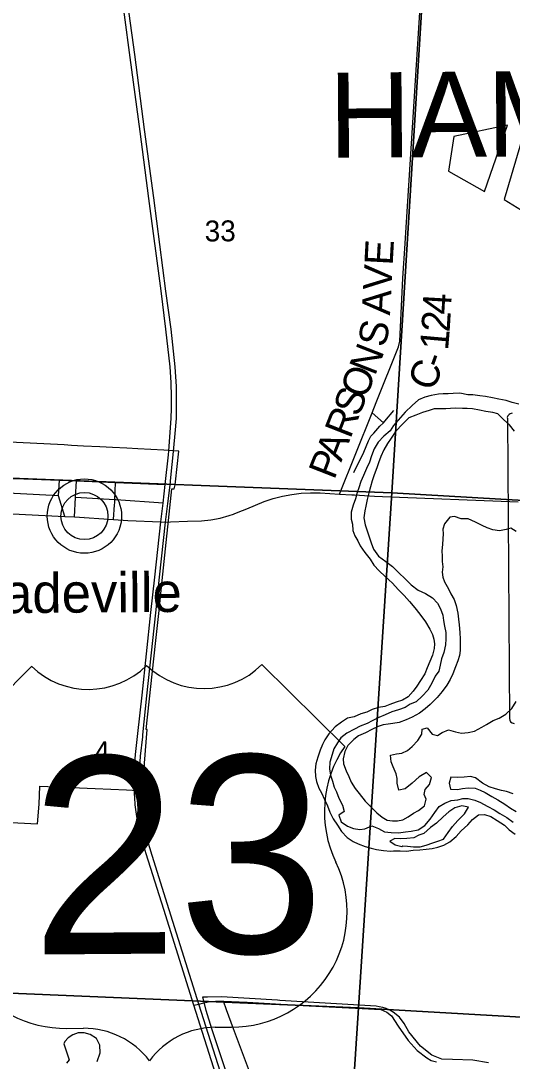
# Model space of a CAD drawing. Extents: x 114604 to 551442, y 316898 to 567001.
# Drawn here: x 204563 to 209759, y 333844 to 344839 of the extents above; entities that cross this region are included whole.
import ezdxf

# ---------------------------------------------------------------- set-up
doc = ezdxf.new("R2010")
doc.units = 0
for name, color, linetype in [('_CIVIL_CONSTRUCTION', 7, 'Continuous'), ('DV_X_County_Line', 7, 'Continuous'), ('GE_P_Alignment_1000_Cardinal_Points', 7, 'Continuous'), ('GE_P_Alignment_1000_Stations', 7, 'Continuous'), ('GE_P_Alignment_100_Stations', 7, 'Continuous'), ('GE_P_Alignment_500_Bearings', 7, 'Continuous'), ('GE_P_Alignment_500_Cardinal_Points', 7, 'Continuous'), ('GE_P_Alignment_500_Curve_Data', 7, 'Continuous'), ('GE_P_Alignment_500_Stations', 7, 'Continuous'), ('GE_X_Alignment', 7, 'Continuous'), ('MT_X_Edge_Line', 7, 'Continuous'), ('PM_P_CL_Double_Solid', 7, 'Continuous'), ('PM_X_Dotted_Line', 7, 'Continuous'), ('PV_X_Curb', 7, 'Continuous'), ('RD_X_RR_1', 7, 'Continuous'), ('SN_P_Signs', 7, 'Continuous')]:
    doc.layers.add(name, color=color, linetype=linetype)

msp = doc.modelspace()

# ---------------------------------------------------------------- linework, layer by layer
at = {"layer": '_CIVIL_CONSTRUCTION'}
for p, q in [((208090, 339829), (208302, 339817)), ((206094, 339542), (206146, 339544))]:
    msp.add_line(p, q, dxfattribs=at)
for points in [[(206818, 339628), (206860, 339645), (206952, 339683), (207043, 339722), (207138, 339758), (207232, 339790), (207329, 339815), (207428, 339833), (207526, 339846), (207626, 339850), (207729, 339849), (207932, 339838), (208064, 339830), (208090, 339829)], [(208302, 339817), (208386, 339813), (209824, 339754)], [(204265, 339638), (205029, 339601), (205130, 339596), (205544, 339568), (205696, 339559), (206045, 339544), (206094, 339542)], [(206146, 339544), (206324, 339550), (206472, 339554), (206572, 339564), (206670, 339582), (206766, 339610), (206813, 339626), (206818, 339628)]]:
    msp.add_lwpolyline(points, dxfattribs=at)
at = {"layer": 'DV_X_County_Line'}
for points in [[(209695, 340825), (209617, 340840), (209551, 340856), (209477, 340870), (209417, 340875), (209343, 340885), (209289, 340888), (209205, 340904), (209135, 340899), (209083, 340897), (209031, 340897), (208980, 340895), (208902, 340880), (208834, 340862), (208770, 340835), (208701, 340773), (208627, 340704), (208504, 340563), (208469, 340507), (208403, 340450), (208343, 340386), (208300, 340314), (208272, 340241), (208249, 340175), (208217, 340107), (208188, 340035), (208158, 339972), (208139, 339904), (208121, 339854), (208101, 339788), (208078, 339720), (208056, 339645), (208057, 339573), (208069, 339521), (208073, 339453), (208094, 339395), (208126, 339344), (208152, 339290), (208201, 339220), (208259, 339148), (208297, 339086), (208354, 339027), (208416, 338965), (208492, 338895), (208555, 338830), (208617, 338766), (208673, 338702), (208730, 338634), (208782, 338569), (208842, 338487), (208887, 338409), (208915, 338355), (208931, 338305), (208936, 338255), (208934, 338205), (208916, 338135), (208889, 338069), (208861, 338001), (208834, 337936), (208790, 337868), (208752, 337806), (208713, 337755), (208659, 337695), (208598, 337658), (208534, 337638), (208466, 337612), (208412, 337593), (208344, 337581), (208279, 337562), (208221, 337532), (208157, 337514), (208089, 337485), (208019, 337469), (207954, 337428), (207886, 337376), (207821, 337303), (207777, 337241), (207753, 337191), (207730, 337132), (207704, 337056), (207683, 336988), (207675, 336920), (207680, 336854), (207690, 336800), (207716, 336730), (207741, 336680), (207773, 336608), (207807, 336542), (207830, 336476), (207866, 336406), (207912, 336337), (207953, 336271), (208013, 336209), (208079, 336167), (208131, 336140), (208203, 336112), (208267, 336094), (208325, 336081), (208397, 336069), (208471, 336062)], [(209606, 340684), (209554, 340698), (209482, 340711), (209414, 340725), (209338, 340739), (209284, 340742), (209232, 340742), (209162, 340745), (209108, 340743), (209056, 340739), (209004, 340737), (208935, 340738), (208881, 340722), (208809, 340699), (208739, 340671), (208665, 340642), (208600, 340578), (208528, 340503), (208479, 340429), (208441, 340371), (208402, 340306), (208370, 340236), (208347, 340168), (208329, 340114), (208300, 340041), (208278, 339977), (208260, 339913), (208243, 339851), (208225, 339781), (208210, 339710), (208200, 339660), (208192, 339588), (208203, 339514), (208225, 339450), (208246, 339386), (208268, 339322), (208292, 339254), (208347, 339183), (208423, 339125), (208495, 339072), (208559, 339004), (208626, 338942), (208692, 338878), (208764, 338821), (208844, 338785), (208915, 338742), (208971, 338686), (209001, 338624), (209024, 338558), (209034, 338502), (209044, 338442), (209057, 338376), (209059, 338306), (209053, 338244), (209038, 338162), (209010, 338098), (208999, 338031), (208983, 337965), (208944, 337913), (208908, 337839), (208867, 337766), (208807, 337700), (208742, 337641), (208680, 337617), (208626, 337581), (208556, 337556), (208486, 337536), (208415, 337503), (208349, 337475), (208277, 337442), (208226, 337414), (208150, 337383), (208090, 337353), (208012, 337310), (207947, 337262), (207911, 337208), (207874, 337145), (207854, 337085), (207832, 337005), (207829, 336935), (207839, 336867), (207858, 336805), (207878, 336741), (207900, 336689), (207927, 336623), (207965, 336549), (207983, 336483), (207926, 336445), (207952, 336373), (208016, 336327), (208082, 336302), (208148, 336294), (208200, 336300), (208276, 336331), (208344, 336303), (208410, 336268), (208480, 336260), (208558, 336258), (208630, 336269), (208692, 336275), (208766, 336288)], [(209829, 340786), (209759, 340807), (209695, 340825)], [(209783, 340501), (209731, 340569), (209670, 340622), (209606, 340684)], [(208766, 336288), (208835, 336334), (208893, 336403), (208940, 336471), (208988, 336535), (209046, 336570), (209115, 336600), (209185, 336607), (209237, 336619), (209293, 336621), (209365, 336604), (209425, 336578), (209495, 336539)], [(209296, 336529), (209228, 336543), (209152, 336522), (209088, 336480), (209028, 336428), (208959, 336361), (208895, 336313), (208824, 336252), (208772, 336232), (208720, 336205), (208644, 336199), (208580, 336193), (208518, 336198), (208467, 336170), (208523, 336130), (208591, 336112)], [(208591, 336112), (208601, 336119), (208653, 336115), (208717, 336109), (208787, 336108), (208851, 336126), (208920, 336153), (208972, 336169), (209034, 336191), (209083, 336260), (209129, 336324), (209185, 336388), (209256, 336457), (209296, 336529)], [(209495, 336539), (209503, 336535), (209569, 336501), (209630, 336461), (209702, 336418), (209768, 336370)], [(208471, 336062), (208503, 336068), (208575, 336068), (208643, 336065), (208713, 336073), (208783, 336076), (208849, 336084), (208913, 336092), (208973, 336105), (209036, 336127), (209098, 336162), (209168, 336218), (209221, 336279), (209289, 336343), (209340, 336399), (209402, 336446), (209468, 336452), (209534, 336429), (209602, 336389), (209678, 336339), (209728, 336290), (209789, 336244)]]:
    msp.add_lwpolyline(points, dxfattribs=at)
at = {"layer": 'GE_P_Alignment_1000_Cardinal_Points'}
for p, q in [((208278, 340697), (208397, 340592)), ((205557, 339777), (205141, 339802)), ((205544, 339568), (205554, 339723))]:
    msp.add_line(p, q, dxfattribs=at)
for points in [[(208084, 340065), (208191, 340282), (208241, 340400), (208263, 340448), (208295, 340482), (208361, 340554), (208397, 340592), (208411, 340608), (208507, 340722)], [(204326, 340003), (204437, 340002), (204501, 340001), (204971, 339983), (205151, 339976)], [(205029, 339601), (204962, 339818), (204971, 339983)], [(205130, 339596), (205141, 339802), (205151, 339976)], [(205151, 339976), (205566, 339961), (206090, 339937)], [(205554, 339723), (205556, 339744), (205557, 339777), (205566, 339961)], [(204962, 339818), (204425, 339848), (204274, 339856)], [(206067, 339743), (205571, 339776), (205557, 339777)], [(207356, 331404), (207410, 331406), (207824, 331419), (207653, 331891), (207380, 332658), (207243, 333036), (207025, 333622), (206813, 334185), (206738, 334385), (206705, 334477)]]:
    msp.add_lwpolyline(points, dxfattribs=at)
at = {"layer": 'GE_P_Alignment_1000_Stations'}
for p, q in [((205981, 338961), (206045, 339544)), ((206031, 338961), (206094, 339542))]:
    msp.add_line(p, q, dxfattribs=at)
for points in [[(206182, 340326), (206196, 340477), (206208, 340636), (206209, 340798), (206208, 340976), (206197, 341181), (206152, 341582), (206097, 341982), (205970, 342969), (205872, 343691), (205768, 344484), (205650, 345353), (205382, 347391), (205104, 349623), (205005, 350415), (204967, 350703), (204739, 352561), (204719, 352732)], [(206124, 340251), (206128, 340293), (206152, 340637), (206157, 340746), (206157, 340864), (206154, 341016), (206143, 341181), (206098, 341580), (206046, 341986), (205916, 342960), (205824, 343668), (205718, 344453), (205599, 345356), (205331, 347383), (205052, 349604), (204952, 350404), (204916, 350706), (204688, 352542), (204683, 352579)], [(206150, 340012), (206179, 340289), (206182, 340326)], [(206045, 339544), (206067, 339743), (206090, 339937), (206124, 340251)], [(206094, 339542), (206119, 339739), (206141, 339933), (206150, 340012)], [(205767, 336631), (205765, 336667), (205761, 336775), (205763, 336892), (205775, 337084), (205800, 337307), (205846, 337711), (205939, 338585), (205981, 338961)], [(205852, 337273), (205854, 337294), (205897, 337707), (205990, 338581), (206031, 338961)], [(205820, 336639), (205815, 336698), (205815, 336827), (205828, 337066), (205852, 337273)], [(207213, 331853), (207164, 332008), (206969, 332619), (206647, 333636), (206394, 334435), (206074, 335447), (205889, 336035), (205837, 336213), (205812, 336322), (205791, 336431), (205773, 336554), (205767, 336631)], [(206446, 334448), (206132, 335443), (205951, 336017), (205904, 336181), (205870, 336298), (205850, 336411), (205826, 336563), (205820, 336639)], [(207331, 331656), (207216, 332020), (207021, 332632), (206700, 333649), (206446, 334448)]]:
    msp.add_lwpolyline(points, dxfattribs=at)
at = {"layer": 'GE_P_Alignment_100_Stations'}
for points in [[(204111, 336384), (204741, 336353), (204757, 336559), (204765, 336751), (205351, 336726), (205679, 336712), (205872, 336703), (205871, 336995), (205899, 337348), (205888, 337349), (205986, 338257), (206021, 338576), (206059, 338925), (206159, 339892), (206185, 339893), (206196, 339935), (206199, 339967), (206235, 340292), (206076, 340300), (205800, 340315), (205684, 340321), (205532, 340329), (205399, 340336), (205225, 340345), (205100, 340351), (205021, 340357), (204082, 340403)], [(209510, 333828), (209344, 333856), (209129, 333861), (209016, 333864), (208908, 333909), (208791, 334002), (208665, 334156), (208616, 334241), (208566, 334309), (208501, 334363), (208464, 334383), (208426, 334401), (208392, 334412), (208352, 334420), (208321, 334424), (207301, 334486), (207278, 334488), (206685, 334524), (206536, 334522), (206484, 334522), (206520, 334384), (206579, 334189), (206628, 334042), (206800, 333525)]]:
    msp.add_lwpolyline(points, dxfattribs=at)
at = {"layer": 'GE_P_Alignment_500_Bearings'}
for points in [[(208628, 342485), (208628, 342490), (208790, 345040), (208827, 345709), (208918, 347356), (208993, 348382)], [(207932, 339838), (208278, 340697), (208321, 340807), (208556, 341393), (208570, 341454), (208604, 342121), (208628, 342485)], [(206394, 334435), (206446, 334448), (206497, 334462), (206561, 334475), (206622, 334480), (206705, 334477), (206955, 334467), (207613, 334429), (208171, 334400), (208371, 334390), (208435, 334363), (208484, 334323), (208554, 334215), (208660, 334063), (208754, 333958), (208858, 333878), (208904, 333852), (208958, 333838)]]:
    msp.add_lwpolyline(points, dxfattribs=at)
at = {"layer": 'GE_P_Alignment_500_Cardinal_Points'}
for p, q in [((204675, 338017), (203811, 337141)), ((207988, 337171), (207112, 338035)), ((205051, 334191), (205225, 334192)), ((206617, 334202), (206791, 334203))]:
    msp.add_line(p, q, dxfattribs=at)
for centre, radius, start, end in [((205280, 338643), 870, 225.9863, 314.8403), ((206498, 338652), 870, 225.9863, 314.8403), ((208991, 336479), 1218, 145.4124, 205.8662), ((205029, 335409), 1218, 155.2452, 271.0516), ((206796, 335422), 1218, 269.7751, 25.5814), ((205231, 333322), 870, 37.2832, 90.4133), ((206624, 333332), 870, 90.4133, 143.5434)]:
    msp.add_arc(centre, radius, start, end, dxfattribs=at)
at = {"layer": 'GE_P_Alignment_500_Curve_Data'}
msp.add_line((209708, 340636), (209731, 337466), dxfattribs=at)
for centre, major_axis, start_param, end_param in [((209768, 340644), (60.5, 0.4), 1.712693, 3.28349), ((209792, 337460), (61, 0.4), 3.00124, 4.508301)]:
    msp.add_ellipse(centre, major_axis=major_axis, ratio=0.8, start_param=start_param, end_param=end_param, dxfattribs=at)
at = {"layer": 'GE_X_Alignment'}
for radius in [393, 249]:
    msp.add_circle((205236, 339605), radius, dxfattribs=at)
at = {"layer": 'MT_X_Edge_Line'}
for points in [[(209711, 343736), (209141, 343617), (209087, 343251), (209467, 343036)], [(209467, 343036), (209711, 343736)], [(209885, 343666), (209676, 342949), (209857, 342837), (209897, 342833), (210273, 343211)], [(209800, 339443), (209744, 339477), (209694, 339462), (209624, 339450), (209554, 339459), (209496, 339479), (209441, 339505), (209371, 339540), (209295, 339576), (209221, 339577), (209150, 339599), (209098, 339592), (209045, 339522), (209027, 339468), (209028, 339416), (209026, 339366), (209022, 339306), (209015, 339236), (209017, 339180), (209020, 339124), (209024, 339070), (209020, 339013), (209025, 338959), (209043, 338909), (209084, 338837), (209112, 338784), (209144, 338722), (209165, 338660), (209185, 338580), (209192, 338516), (209200, 338455), (209207, 338375), (209209, 338305), (209208, 338185), (209203, 338133), (209183, 338075), (209161, 338011), (209132, 337939), (209102, 337877), (209067, 337819), (209017, 337752), (208965, 337686), (208892, 337614), (208840, 337568), (208778, 337521), (208703, 337481), (208637, 337450), (208565, 337424), (208497, 337412), (208447, 337405), (208395, 337399), (208343, 337381), (208275, 337350), (208207, 337314), (208135, 337283), (208084, 337243), (208020, 337179), (207990, 337117), (207973, 337039), (207977, 336985), (208004, 336913), (208030, 336853), (208055, 336794), (208097, 336726), (208140, 336672), (208204, 336591), (208275, 336521), (208329, 336468), (208384, 336424), (208436, 336391), (208494, 336385), (208548, 336384), (208602, 336394), (208658, 336426), (208714, 336465), (208767, 336493), (208831, 336541), (208851, 336613), (208828, 336663), (208840, 336715), (208884, 336767), (208905, 336843), (208853, 336895), (208775, 336850), (208703, 336782), (208628, 336724), (208562, 336707), (208543, 336781), (208543, 336831), (208533, 336881), (208500, 336956), (208480, 337006), (208471, 337078), (208535, 337092), (208591, 337101), (208653, 337129), (208703, 337171)], [(208703, 337171), (208760, 337232), (208802, 337300), (208806, 337352), (208860, 337366), (208914, 337299), (208970, 337285), (209020, 337317), (209086, 337346), (209158, 337326), (209224, 337309), (209292, 337317), (209362, 337331), (209438, 337374), (209488, 337402), (209558, 337443), (209622, 337469), (209691, 337513), (209755, 337570), (209802, 337644)], [(209769, 336669), (209699, 336693), (209645, 336706), (209583, 336722), (209514, 336743), (209444, 336783), (209370, 336840), (209317, 336854), (209251, 336844), (209177, 336841), (209111, 336845), (209094, 336781), (209106, 336719), (209180, 336717), (209234, 336726), (209292, 336734), (209366, 336728), (209421, 336707), (209473, 336683), (209543, 336642), (209607, 336606), (209680, 336561), (209742, 336519), (209802, 336484)], [(205372, 333842), (205402, 333933), (205400, 334013), (205364, 334083), (205298, 334127), (205234, 334145), (205168, 334143), (205112, 334123), (205064, 334091), (205028, 334051), (205018, 334029)], [(205018, 334029), (205075, 333859)], [(205075, 333859), (205045, 333823)]]:
    msp.add_lwpolyline(points, dxfattribs=at)
at = {"layer": 'PM_X_Dotted_Line'}
msp.add_line((205236, 339605), (205236, 339605), dxfattribs=at)
at = {"layer": 'SN_P_Signs'}
for points in [[(203568, 345444), (208815, 345168), (208486, 339851), (204088, 340018)], [(204088, 340018), (208486, 339851), (208133, 334409), (202949, 334626)]]:
    msp.add_lwpolyline(points, dxfattribs=at)
for points in [[(208815, 345168), (214212, 344849), (214210, 344829), (213887, 339536), (208486, 339851)], [(208486, 339851), (213887, 339536), (213546, 334098), (208133, 334409)], [(202949, 334626), (208133, 334409), (207790, 329100), (202938, 329361), (202888, 329456), (202854, 329516), (202804, 329592), (202686, 329774)], [(208133, 334409), (213546, 334098), (213253, 328806), (207790, 329100)]]:
    msp.add_lwpolyline(points, close=True, dxfattribs=at)

# ---------------------------------------------------------------- texts
at = {"layer": '_CIVIL_CONSTRUCTION'}
msp.add_text('Shadeville', height=417, rotation=0.4133, dxfattribs=at).set_placement((203694, 338574))
at = {"layer": 'GE_P_Alignment_500_Cardinal_Points'}
msp.add_text('23', height=2088.4, rotation=0.4133, dxfattribs=at).set_placement((204675, 334971))
at = {"layer": 'GE_P_Alignment_500_Stations'}
msp.add_text('HAMILTON', height=900.1, rotation=0.4134, dxfattribs=at).set_placement((207823, 343391))
at = {"layer": 'PM_P_CL_Double_Solid'}
for s, rotation, p in [('E', 86.9092, (208495, 342250)), ('V', 86.907, (208481, 341986)), ('A', 86.9032, (208467, 341723)), ('4', 86.7323, (209108, 341729)), ('2', 86.538, (209097, 341543)), ('S', 78.9238, (208419, 341381)), ('1', 84.997, (209080, 341350)), ('N', 68.6484, (208307, 341078)), ('-', 70.2917, (209021, 341152)), ('C', 68.0141, (208924, 340912)), ('O', 68.6181, (208211, 340832)), ('S', 68.619, (208137, 340644)), ('R', 68.6211, (208047, 340414)), ('A', 68.6181, (207951, 340169)), ('P', 68.619, (207877, 339980))]:
    msp.add_text(s, height=300, rotation=rotation, dxfattribs=at).set_placement(p)
at = {"layer": 'PV_X_Curb'}
for s, rotation, p in [('33', 0.4134, (206508, 342507)), ('4', 0.4133, (205340, 337004))]:
    msp.add_text(s, height=221, rotation=rotation, dxfattribs=at).set_placement(p)
at = {"layer": 'RD_X_RR_1'}
for s, p in [('0', (205908, 336009)), ('/', (205908, 336009)), ('23', (205703, 335800))]:
    msp.add_text(s, height=1, rotation=0.4133, dxfattribs=at).set_placement(p)

doc.saveas('drawing.dxf')
